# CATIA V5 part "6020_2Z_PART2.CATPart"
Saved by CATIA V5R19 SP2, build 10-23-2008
Part number: 6020_2Z_PART2
Bounding box of the stored display mesh (mm): x 0 to 24, y -74.81 to 74.81, z -74.81 to 74.81
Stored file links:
  G:\EU_thinkMotion\CFAO_2010\MMS_groupe2\MMS_groupe2\OK\nrosalie\nrosalie_cfao_support_d_arme_legere_final\6020_2Z_PART2.CATPart
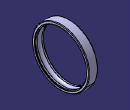
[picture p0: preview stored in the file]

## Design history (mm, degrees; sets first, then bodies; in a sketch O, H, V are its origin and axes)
Set1
  Point1: (0, 0, 0)
  Point2: (1, 0, 0)
  Point3: (0, 1, 0)
  Plane1: type 3Points, Element1 Point1, Element2 Point2, Element3 Point3
Body1 (main body)
  Sketch1 on Plane1, origin (0, 0, 0), H (1, 0, 0), V (0, 1, 0)
    point P1 (0, 73.5)
    point P2 (0, 69)
    line L1 (0, 73.5) -> (0, 69)
    point P3 (0, 69)
    point P4 (0.4628, 69)
    line L2 (0, 69) -> (0.4628, 69)
    arc A1 centre (1.0578, 69) radius 0.595 from (1.6528, 69) to (0.4628, 69) ccw
    point P5 (1.6528, 69)
    point P6 (2.0054, 67)
    line L3 (1.6528, 69) -> (2.0054, 67)
    point P7 (2.0054, 67)
    point P8 (5.9501, 67)
    line L4 (2.0054, 67) -> (5.9501, 67)
    arc A2 centre (12, 62.5) radius 7.54 from (18.0499, 67) to (5.9501, 67) ccw
    point P9 (18.0499, 67)
    point P10 (21.9946, 67)
    line L5 (18.0499, 67) -> (21.9946, 67)
    point P11 (21.9946, 67)
    point P12 (22.3472, 69)
    line L6 (21.9946, 67) -> (22.3472, 69)
    arc A3 centre (22.9422, 69) radius 0.595 from (23.5372, 69) to (22.3472, 69) ccw
    point P13 (23.5372, 69)
    point P14 (24, 69)
    line L7 (23.5372, 69) -> (24, 69)
    point P15 (24, 69)
    point P16 (24, 73.5)
    line L8 (24, 69) -> (24, 73.5)
    arc A4 centre (22.5, 73.5) radius 1.5 from (24, 73.5) to (22.5, 75) ccw
    point P17 (22.5, 75)
    point P18 (1.5, 75)
    line L9 (22.5, 75) -> (1.5, 75)
    arc A5 centre (1.5, 73.5) radius 1.5 from (1.5, 75) to (0, 73.5) ccw
    point P19 (22.5, 0)
    point P20 (1.5, 0)
    axis line L10 (22.5, 0) -> (1.5, 0)
    point P21 (0, 73.5)
    point P22 (0, 69)
    point P23 (0, 69)
    point P24 (0.4628, 69)
    point P25 (1.6528, 69)
    point P26 (0.4628, 69)
    point P27 (1.6528, 69)
    point P28 (2.0054, 67)
    point P29 (2.0054, 67)
    point P30 (5.9501, 67)
    point P31 (18.0499, 67)
    point P32 (5.9501, 67)
    point P33 (18.0499, 67)
    point P34 (21.9946, 67)
    point P35 (21.9946, 67)
    point P36 (22.3472, 69)
    point P37 (23.5372, 69)
    point P38 (22.3472, 69)
    point P39 (23.5372, 69)
    point P40 (24, 69)
    point P41 (24, 69)
    point P42 (24, 73.5)
    point P43 (24, 73.5)
    point P44 (22.5, 75)
    point P45 (22.5, 75)
    point P46 (1.5, 75)
    point P47 (1.5, 75)
    point P48 (0, 73.5)
    coincidence: P21 P48, P22 P23, P24 P26, P25 P27, P28 P29, P30 P32, P31 P33, P34 P35, P36 P38, P37 P39, P40 P41, P42 P43, P44 P45, P46 P47
  Shaft1: profile Sketch1, axis Sketch1.L10, angle 360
